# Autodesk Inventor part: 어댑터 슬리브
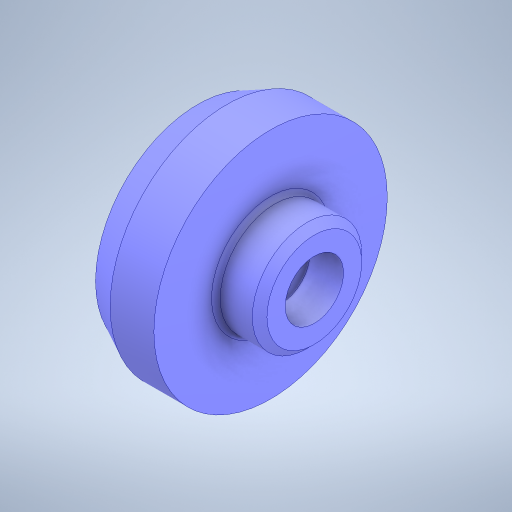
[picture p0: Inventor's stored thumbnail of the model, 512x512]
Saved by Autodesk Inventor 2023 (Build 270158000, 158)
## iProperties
Created: 2026-07
Part Number: 어댑터 슬리브
Material: 강철, 탄소
Document SubType Name: Modeling
Designer: home
Density: 7.87 g/cm^3
Appearance: 기본값
Author: jhkim
Sending System: Autodesk Inventor 2027
Preprocessor: ST-DEVELOPER v20.1
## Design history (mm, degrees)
feature "솔리드1"
node "솔리드2"
